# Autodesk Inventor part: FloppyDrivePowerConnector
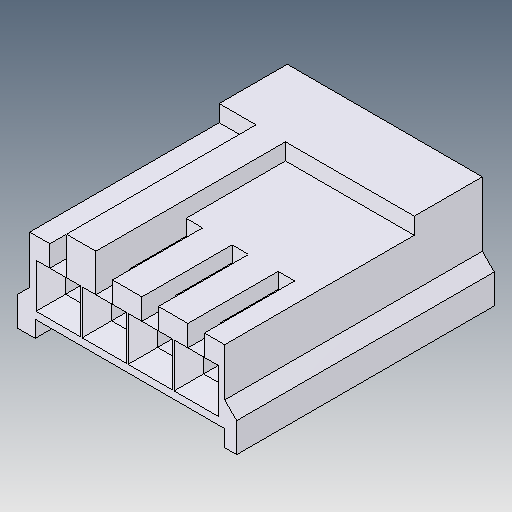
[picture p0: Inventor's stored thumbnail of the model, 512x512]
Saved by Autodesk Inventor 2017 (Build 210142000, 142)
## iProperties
Created: 2006-09
Part Number: FloppyDrivePowerConnector
Material: Generic
Document SubType Name: Modeling
Designer: DanielSeverino
Categories: <MemberInstance><Categories><Category DisplayName="" Mnemonic="CABLEANDHARNESS" InternalName="e4a7e005-5e42-4d16-b293-125e7f0d0512"><Category DisplayName="" Mne
Density: 1 g/cm^3
Appearance: Default
GlobalPropertyList: <PropertyList/>
Author: Prof. Daniel Severino
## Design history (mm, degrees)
feature "Solid1"
sketch "Sketch1"
  geometry: L1 (1.1, -1.75)-(1.1, -2.05) reference; L2 (0.5, -1.75)-(1.1, -1.75) reference; L3 (0.5, -1.75)-(0.5, -3.95) reference; L4 (0.5, -3.95)-(2.6, -3.95) reference; L5 (2.6, -1.75)-(2.6, -3.95) reference; L6 (2, -1.75)-(2.6, -1.75) reference; L7 (2, -1.75)-(2, -2.05) reference; L8 (2, -2.05)-(1.1, -2.05) reference; L9 (1.95, -2.85)-(1.95, -3.65) reference; L10 (1.95, -3.65)-(1.15, -3.65) reference; L11 (1.15, -3.65)-(1.15, -2.85) reference; L12 (1.15, -2.85)-(1.95, -2.85) reference; L13 (3.6, -1.75)-(3.6, -2.05) reference; L14 (3, -1.75)-(3.6, -1.75) reference; L15 (3, -1.75)-(3, -3.95) reference; L16 (3, -3.95)-(5.1, -3.95) reference; L17 (5.1, -1.75)-(5.1, -3.95) reference; L18 (4.5, -1.75)-(5.1, -1.75) reference; L19 (4.5, -1.75)-(4.5, -2.05) reference; L20 (4.5, -2.05)-(3.6, -2.05) reference; L21 (4.45, -2.85)-(4.45, -3.65) reference; L22 (4.45, -3.65)-(3.65, -3.65) reference; L23 (3.65, -3.65)-(3.65, -2.85) reference; L24 (3.65, -2.85)-(4.45, -2.85) reference; L25 (6.1, -1.75)-(6.1, -2.05) reference; L26 (5.5, -1.75)-(6.1, -1.75) reference; L27 (5.5, -1.75)-(5.5, -3.95) reference; L28 (5.5, -3.95)-(7.6, -3.95) reference; L29 (7.6, -1.75)-(7.6, -3.95) reference; L30 (7, -1.75)-(7.6, -1.75) reference; L31 (7, -1.75)-(7, -2.05) reference; L32 (7, -2.05)-(6.1, -2.05) reference; L33 (6.95, -2.85)-(6.95, -3.65) reference; L34 (6.95, -3.65)-(6.15, -3.65) reference; L35 (6.15, -3.65)-(6.15, -2.85) reference; L36 (6.15, -2.85)-(6.95, -2.85) reference; L37 (8.6, -1.75)-(8.6, -2.05) reference; L38 (8, -1.75)-(8.6, -1.75) reference; L39 (8, -1.75)-(8, -3.95) reference; L40 (8, -3.95)-(10.1, -3.95) reference; L41 (10.1, -1.75)-(10.1, -3.95) reference; L42 (9.5, -1.75)-(10.1, -1.75) reference; L43 (9.5, -1.75)-(9.5, -2.05) reference; L44 (9.5, -2.05)-(8.6, -2.05) reference; L45 (9.45, -2.85)-(9.45, -3.65) reference; L46 (9.45, -3.65)-(8.65, -3.65) reference; L47 (8.65, -3.65)-(8.65, -2.85) reference; L48 (8.65, -2.85)-(9.45, -2.85) reference; L49 (8, -1.75)-(10.1, -3.95); L50 (5.5, -1.75)-(7.6, -3.95); 3 further points
  constraints: 4 end point, 2 midpoint, 1 parallel
  dimensions: "d0" = 2.5 distance of point (9.05, -2.85) point (6.55, -2.85) (derived)
  node "Projected Loop1"
  node "Projected Loop2"
  node "Projected Loop3"
  node "Projected Loop4"
node "1"
node "2"
node "3"
node "4"
body "Solid2"
